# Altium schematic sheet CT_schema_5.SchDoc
size 227 x 258 mm
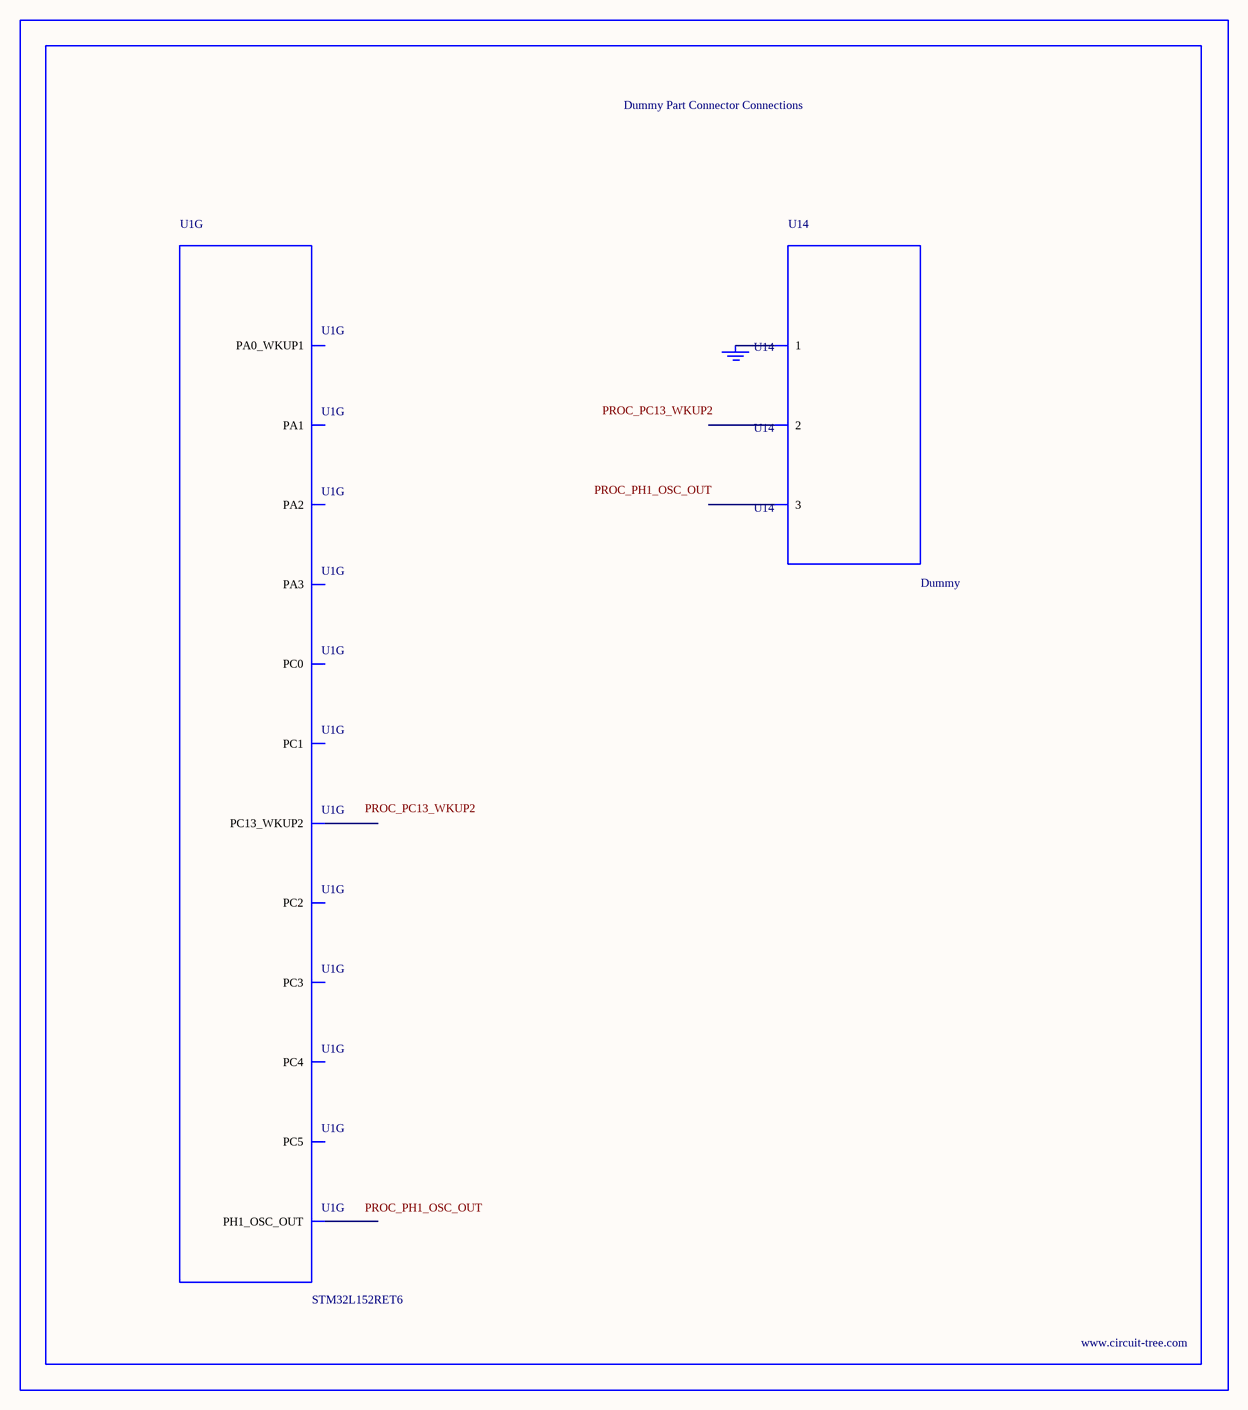
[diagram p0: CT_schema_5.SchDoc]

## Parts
BORDER4  (no value)
GND_INSTANCE_4_0  (no value)
U1  STM32L152RET6  [LQFP64]  (part G of 7)
U14  Dummy  [DUMMY_PACKAGE_112]

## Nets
NetGND_INSTANCE_4_0_0: GND_INSTANCE_4_0.0(GND) U14.1

Not connected (* = marked no-connect by the designer): U1 2(PC13_WKUP2) 6(PH1_OSC_OUT) 8(PC0) 9(PC1) 10(PC2) 11(PC3) 14(PA0_WKUP1) 15(PA1) 16(PA2) 17(PA3) 24(PC4) 25(PC5); U14 2 3

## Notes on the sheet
- Labels drawn without touching a wire or pin: PROC_PC13_WKUP2, PROC_PH1_OSC_OUT

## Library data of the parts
BORDER4 = BORDER_PAGE4
GND_INSTANCE_4_0 = GND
